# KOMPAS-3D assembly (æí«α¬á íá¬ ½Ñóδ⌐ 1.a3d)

Referenced files in D:\АСКОН работа\Конкурс HOME\06_Сюваев_Сборная модель танка Т90\ДЕТАЛИ\КОРПУС\МЕТАЛЛ\КОРПУС ШТАМПОВКА\БАКИ\: бак левый 1.m3d
Referenced files in D:\АСКОН работа\Конкурс HOME\06_Сюваев_Сборная модель танка Т90\ДЕТАЛИ\ОБЩИЕ ДЕТАЛИ\: шарниры ящиков.m3d, ручки баков.m3d, замки ящиков.m3d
